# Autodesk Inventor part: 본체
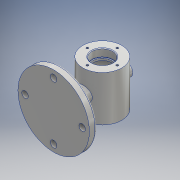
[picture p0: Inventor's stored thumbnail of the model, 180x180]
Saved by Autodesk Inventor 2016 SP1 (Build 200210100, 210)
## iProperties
Created: 2018-12
Part Number: 본체
Material: 알루미늄 6061
Document SubType Name: Modeling
Designer: basic
Mass: 683.222 g
Surface Area: 556.118 cm^2
Volume: 253.045 cm^3
Density: 2.7 g/cm^3
Appearance: 알루미늄 - 평지
Title: 본체
Author: 481208V1013
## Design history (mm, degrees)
sketch "스케치1"
  geometry: C1 r 30 at (0, 0); 1 further point
  constraints: 1 centre point, 1 coincident
  dimensions: "d0" = 60 diameter of C1
extrude "돌출1" new body sketch "스케치1" distance "d1" = 70; taper "d2" = 0 deg
node "작업 평면1"
sketch "스케치2"
  geometry: L1 (30, 70)-(-30, 70) reference; L2 (-30, 0)-(30, 0) reference; L3 (-30, 0)-(30, 0) reference; L4 (30, 70)-(-30, 70) reference; C1 r 55 at (0, 35); 1 further point
  constraints: 1 centre point
  dimensions: "d5" = 110 diameter of C1; "d6" = 35 distance from line of C1.centre L1; "d7" = 46.09772 distance of L1.start C1.centre
extrude "돌출2" join sketch "스케치2" distance "d8" = 10; taper "d9" = 0 deg
sketch "스케치3"
  geometry: L1 (-30, 0)-(30, 0) reference; L2 (0, 0)-(16, 0); L3 (16, 0)-(16, 12); L4 (16, 12)-(14, 12); L5 (30, 70)-(-30, 70) reference; L6 (25, 35)-(25, 15); L7 (25, 15)-(14, 15); L8 (14, 15)-(14, 12); L9 (16, 70)-(16, 58); L10 (14, 55)-(14, 58); L11 (16, 58)-(14, 58); L12 (25, 55)-(14, 55); L13 (25, 35)-(25, 55); L14 (16, 70)-(0, 70); L15 (0, 0)-(0, 70)
  constraints: 26 end point, 3 parallel, 3 perpendicular, 2 vertical, 1 collinear, 1 point on line
  dimensions: "d29" = 12 distance of L2.end L3.end; "d40" = 11 distance of L6.end L7.end; "d41" = 32 diameter of L3 L15; "d42" = 28 diameter of L8 L15; "d43" = 32 diameter of L9 L15; "d44" = 28 diameter of L10 L15; "d45" = 15 distance between parallel lines of L12 L5; "d46" = 55 distance between parallel lines of L7 L5; "d47" = 12 distance between parallel lines of L11 L5; "d48" = 0 distance between parallel lines of L14 L5; "d49" = 35 distance from line of L6.start L5
revolve "회전1" sketch "스케치3" stored, may be unused: angle "d50" = 90 deg
node "작업 평면2"
sketch "스케치4"
  geometry: 1 further point
node "직접 편집1"
sketch "스케치5"
  geometry: L1 (12, -52.478)-(55, -64); L2 (55, -75)-(55, -64) reference; L3 (0, -52.478)-(12, -52.478); L4 (0, -52.478)-(0, -64); L5 (55, -64)-(-55, -64) reference; L6 (0, -64)-(55, -64); 1 further point
  constraints: 8 end point, 1 collinear, 1 horizontal, 1 parallel
  dimensions: "d56" = 75 deg angle of L2 L1; "d57" = 12 distance of L3.start L1.start; "d62" = 11.52182 distance between parallel lines of L5 L3
revolve "회전2" sketch "스케치5" stored, may be unused: angle "d63" = 90 deg
sketch "스케치6"
  geometry: C1 r 12 at (0, 0); 1 further point
  constraints: 1 centre point
  dimensions: "d64" = 24 diameter of C1
extrude "돌출3" join sketch "스케치6" stored distance "d65" = 10; taper "d66" = 0 deg
node "작업 평면3"
sketch "스케치7"
  geometry: L1 (30, 70)-(-30, 70) reference; C1 r 10 at (0, 35); 1 further point
  constraints: 1 centre point
  dimensions: "d68" = 20 diameter of C1; "d69" = 35 distance of point (0, 0) C1.centre; "d70" = 35 distance from line of L1 C1.centre
extrude "돌출4" join sketch "스케치7" stored distance "d71" = 10; taper "d72" = 0 deg
sketch "스케치8"
  geometry: L1 (-10, 37)-(10, 37) reference; 2 further points
  dimensions: "d73" = 23 distance of point (0, 0) point (0, 23); "d74" = 14 distance from line of L1 point (0, 23)
hole "구멍1" sketch "스케치8" at (0, 23) diameter "d75" = 3.242; stored, may be unused: countersink angle "d79" = 90 deg, drill point angle "d81" = 118 deg; dims "d76" = 8, "d77" = 4, "d78" = 2, "d80" = 10
sketch "스케치9"
  geometry: C1 r 10 at (0, 0) reference; 2 further points
  dimensions: "d88" = 44 distance of point (0, 44) C1.centre; "d89" = 79 distance of point (0, -35) point (0, 44)
hole "구멍2" sketch "스케치9" at (0, 44) diameter "d90" = 10; stored, may be unused: countersink angle "d94" = 90 deg, drill point angle "d96" = 0 deg; dims "d91" = 8, "d92" = 4, "d93" = 2, "d95" = 10
sketch "스케치10"
  geometry: C1 r 7 at (0, 0); C2 r 55 at (0, -44) reference; 1 further point
  constraints: 1 centre point
  dimensions: "d97" = 14 diameter of C1; "d98" = 44 distance of C1.centre C2.centre; "d99" = 79 distance of point (0, -79) C1.centre
extrude "돌출5" cut sketch "스케치10" stored distance "d100" = 10; taper "d101" = 0 deg
chamfer "모따기1" distance "d105" = 1; stored, may be unused: second distance "d106" = 2, angle "d107" = 45 deg
sketch "스케치11"
  geometry: C1 r 10 at (0, 0) reference; 1 further point
hole "구멍3" sketch "스케치11" at (0, 0) diameter "d108" = 10; stored, may be unused: countersink angle "d112" = 90 deg, drill point angle "d114" = 0 deg; dims "d109" = 8, "d110" = 4, "d111" = 2, "d113" = 10
chamfer "모따기2" distance "d115" = 1; stored, may be unused: second distance "d116" = 2, angle "d117" = 45 deg
fillet "모깎기1" dims "d118" = 3
fillet "모깎기2" dims "d119" = 3
fillet "모깎기3" dims "d120" = 3
fillet "모깎기4" dims "d121" = 0.3
fillet "모깎기5" dims "d122" = 3
node "작업 평면4"
sketch "스케치12"
  geometry: 2 further points
  constraints: 1 other
feature "엠보싱1" sketch "스케치12" dims "d124" = 0.5, "d125" = 0
node "솔리드1"
pattern_circular "원형 패턴1" dims angle "d83" = 360 deg
mirror "대칭1"
pattern_circular "원형 패턴2" dims angle "d103" = 360 deg
node "투영된 루프1"
feature "이동1" dims "d54" = 1
other parameters: "d3" = -75, "d51" = 35, "d52" = 0, "d53" = 0, "d67" = 37, "d123" = -30.5
